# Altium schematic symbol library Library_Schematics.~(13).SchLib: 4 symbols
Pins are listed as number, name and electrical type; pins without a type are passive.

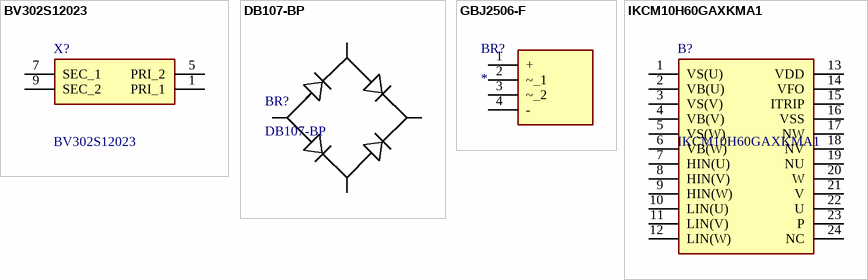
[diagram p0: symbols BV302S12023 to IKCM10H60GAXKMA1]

## BV302S12023
designator X?
2.3VA Encapsulated Transformer 50/60Hz; Manufacturer_Name: Zettler Group; Geometry.Height: 29.8mm
footprint 899_BV302S12023
pins: 1 PRI_1, 5 PRI_2, 7 SEC_1, 9 SEC_2

## DB107-BP
designator BR?
Description; Manufacturer_Name: MCC
footprint 898_DB107-BP (Footprint not found)
pins: 1, 2, 3, 4

## GBJ2506-F
designator BR?
Bridge Rectifier; Manufacturer_Name: Diodes Incorporated; Manufacturer_Part_Number: GBJ2506-F
footprint 996_GBJ_1
pins: 1 +, 2 ~_1, 3 ~_2, 4 -

## IKCM10H60GAXKMA1
designator B?
Intelligent Power Module 3-Ph 600V 10A; Manufacturer_Name: Infineon; Geometry.Height: 5.6mm
footprint 997_IKCM10H60GAXKMA1
pins: 1 VS(U), 2 VB(U), 3 VS(V), 4 VB(V), 5 VS(W), 6 VB(W), 7 HIN(U), 8 HIN(V), 9 HIN(W), 10 LIN(U), 11 LIN(V), 12 LIN(W), 13 VDD, 14 VFO, 15 ITRIP, 16 VSS, 17 NW, 18 NV, 19 NU, 20 W, 21 V, 22 U, 23 P, 24 NC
